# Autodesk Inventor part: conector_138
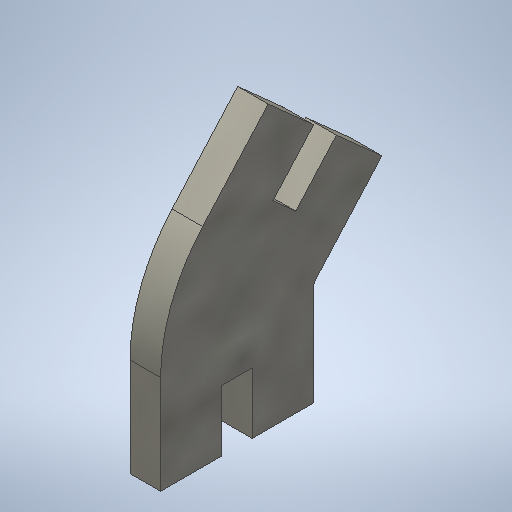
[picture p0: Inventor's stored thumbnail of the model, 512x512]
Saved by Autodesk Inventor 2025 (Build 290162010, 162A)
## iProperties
Created: 2025-02
Part Number: conector_138
Material: Paper
Document SubType Name: Modeling
Designer: BennF
Density: 0.93 g/cm^3
Appearance: Cardboard - Chipboard
Author: BennF
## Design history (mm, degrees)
sketch "Sketch2"
  geometry: L1 (-1, 0)-(-1, -8.061); L2 (-1, -8.061)-(-6, -8.061); L3 (-6, -8.061)-(-6, -3.061); L4 (-6, -3.061)-(-8.5, -3.061); L5 (-8.5, -3.061)-(-8.5, -8.061); L6 (-8.5, -8.061)-(-13.5, -8.061); L7 (-13.5, -8.061)-(-13.5, 0); L8 (-0.745, 0.667)-(4.628, 6.675); L9 (4.628, 6.675)-(0.902, 10.008); L10 (0.902, 10.008)-(-2.432, 6.281); L11 (-2.432, 6.281)-(-4.295, 7.948); L12 (-4.295, 7.948)-(-0.962, 11.675); L13 (-0.962, 11.675)-(-4.689, 15.008); L14 (-4.689, 15.008)-(-10.062, 9); L15 (-2.432, 6.281)-(-6, -3.061); A1 r 1 centre (0, 0) between (-0.745, 0.667) and (-1, 0); A2 r 13.5 centre (0, 0) between (-10.062, 9) and (-13.5, 0); 1 further point
  constraints: 30 end point, 10 perpendicular, 5 equal length, 4 point on circle, 4 point on line, 4 tangent, 2 centre point, 2 coincident, 1 vertical
  dimensions: "d0" = 2.5 distance of L10.end L11.end (= thickness); "d1" = 5 distance of L11.end L12.end (= slot_depth); "d2" = 1 radius of A1; "d3" = 5 distance of L12.end L13.end (= slot_dis_1); "d4" = 138.19 deg angle of L1 L8 (= con_angle_5); "d5" = 10 distance of L10.end L3.end (computed from slot_clearenece)
extrude "Extrusion1" new body sketch "Sketch2" distance "d6" = 2.5 (= thickness); taper "d7" = 0 deg
sketch "laser"
  geometry: L1 (-10.008, 0.902)-(-6.281, -2.432) reference; L2 (-6.281, -2.432)-(-7.948, -4.295) reference; L3 (-7.948, -4.295)-(-11.675, -0.962) reference; L4 (-11.675, -0.962)-(-15.008, -4.689) reference; L5 (-15.008, -4.689)-(-9, -10.062) reference; L6 (0, -13.5)-(8.061, -13.5) reference; L7 (8.061, -13.5)-(8.061, -8.5) reference; L8 (8.061, -8.5)-(3.061, -8.5) reference; L9 (3.061, -8.5)-(3.061, -6) reference; L10 (3.061, -6)-(8.061, -6) reference; L11 (8.061, -6)-(8.061, -1) reference; L12 (8.061, -1)-(0, -1) reference; L13 (-0.667, -0.745)-(-6.675, 4.628) reference; L14 (-6.675, 4.628)-(-10.008, 0.902) reference; A1 r 13.5 centre (0, 0) between (-9, -10.062) and (0, -13.5) reference; A2 r 1 centre (0, 0) between (-0.667, -0.745) and (0, -1) reference; 1 further point
  node "Projected Loop1"
body "Solid1"
other parameters: "thickness" = 2.5 [user parameter; used in 2 equation terms], "clearence" = -0.5 [user parameter], "slot_depth" = 5 [user parameter; used in 1 equation term], "slot_dis_1" = 5 [user parameter; used in 1 equation term], "slot_dis_2" = 12 [user parameter], "slot_clearenece" = 3 [user parameter; used in 1 equation term], "con_angle_1" = 20.34444 [user parameter], "con_angle_2" = 60 deg [user parameter], "con_angle_3" = 12.30959 [user parameter], "con_angle_4" = 19.10633 [user parameter], "con_angle_5" = 138.19 deg [user parameter; used in 1 equation term], "con_angle_6" = 13.04634 [user parameter]
